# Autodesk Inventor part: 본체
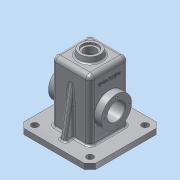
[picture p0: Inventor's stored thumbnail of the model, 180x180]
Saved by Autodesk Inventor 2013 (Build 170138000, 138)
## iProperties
Created: 2016-02
Part Number: 본체
Material: 알루미늄 6061
Document SubType Name: Modeling
Designer: Administrator
Density: 2.71 g/cm^3
Mass: 932.811 g
Surface Area: 1043.48 cm^2
Volume: 344.211 cm^3
Author: Administrator
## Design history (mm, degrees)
sketch "스케치1"
  geometry: L1 (10, 0)-(120, 0); L2 (130, 10)-(130, 120); L3 (120, 130)-(10, 130); L4 (0, 120)-(10, 130); L5 (0, 10)-(0, 120); L6 (130, 120)-(120, 130); L7 (130, 10)-(120, 0); L8 (0, 10)-(10, 0); C1 r 6 at (15, 15); C2 r 6 at (115, 15); C3 r 6 at (115, 115); C4 r 6 at (15, 115); 1 further point
  constraints: 16 end point, 5 perpendicular, 4 centre point, 1 horizontal
extrude "돌출1" new body sketch "스케치1" distance "d19" = 10; taper "d20" = 0 deg
sketch "스케치2"
  geometry: L1 (100, 65)-(100, 38); L2 (92, 30)-(38, 30); L3 (30, 38)-(30, 92); L4 (38, 100)-(92, 100); L5 (100, 92)-(100, 65); A1 r 8 centre (38, 92) between (38, 100) and (30, 92); A2 r 8 centre (92, 92) between (100, 92) and (92, 100); A3 r 8 centre (92, 38) between (92, 30) and (100, 38); A4 r 8 centre (38, 38) between (30, 38) and (38, 30); 1 further point
  constraints: 10 end point, 8 point on circle, 8 tangent, 4 centre point, 3 equal radius, 2 parallel, 1 perpendicular
extrude "돌출2" join sketch "스케치2" distance "d28" = 110; taper "d29" = 0 deg
sketch "스케치3"
  geometry: L1 (-30, 65)-(-30, 100) reference; L2 (-30, 100)-(-100, 100); L3 (-100, 100)-(-100, 30); L4 (-100, 30)-(-30, 30) reference; L5 (-30, 30)-(-30, 65) reference; L6 (-35, 95)-(-35, 65); L7 (-35, 65)-(-35, 35); L8 (-35, 35)-(-95, 35); L9 (-95, 35)-(-95, 95); L10 (-95, 95)-(-35, 95); 1 further point
  constraints: 20 end point, 4 perpendicular, 2 parallel, 2 vertical, 1 horizontal, 4 other
  dimensions: "d34" = 70 distance of L2.end L3.end; "d35" = 70 distance of L3.end L4.end; "d37" = 5 distance between parallel lines of L1 L6
extrude "돌출3" cut sketch "스케치3" distance "d38" = 115; taper "d39" = 0 deg
node "작업 평면1"
sketch "스케치4"
  geometry: L1 (30, 10)-(30, 120) reference; L2 (120, 10)-(10, 10) reference; L3 (0, 0)-(0, 10); L4 (15, 10)-(30, 95.069); L5 (30, 95.069)-(30, 10); L6 (15, 10)-(30, 10)
  constraints: 8 end point, 2 collinear, 2 point on line
  dimensions: "d42" = 10 distance of L3.start L3.end; "d43" = 15 distance of L3.end L4.start
extrude "돌출4" join sketch "스케치4" stored distance "d48" = 10; taper "d49" = 0 deg
node "작업 평면2"
sketch "스케치5"
  geometry: L1 (0, 0)-(-110, 0) reference; L2 (10, -38)-(10, 27); L3 (10, 27)-(-45, 27); L4 (0, -8)-(-110, -8) reference; C1 r 27.5 at (-45, 27)
  constraints: 4 end point, 2 perpendicular, 1 centre point, 1 coincident
  dimensions: "d51" = 65 distance of L2.start L2.end; "d52" = 55 distance of L2.end L3.end; "d53" = 55 diameter of C1
extrude "돌출5" join sketch "스케치5" distance "d54" = 13; taper "d55" = 0 deg
sketch "스케치6"
  geometry: L1 (0, 0)-(0, 60) reference; L2 (0, 60)-(115, 60) reference; L3 (0, 30)-(55, 30); C1 r 27.5 at (55, 30); 1 further point
  constraints: 2 end point, 1 centre point, 1 coincident, 1 midpoint, 1 parallel
  dimensions: "d56" = 55 distance of L3.start L3.end; "d57" = 55 diameter of C1
extrude "돌출6" join sketch "스케치6" distance "d58" = 7; taper "d59" = -45 deg
sketch "스케치7"
  geometry: C1 r 27.5 at (0, 0) reference; C2 r 16 at (0, 0); 1 further point
  constraints: 1 centre point, 1 coincident
  dimensions: "d60" = 32 diameter of C2
extrude "돌출7" cut sketch "스케치7" distance "d61" = 50; taper "d62" = 0 deg
sketch "스케치8"
  geometry: L1 (0, 0)-(-22.5, 0); C1 r 27.5 at (0, 0) reference; 1 further point
  constraints: 2 end point, 1 coincident, 1 horizontal, 1 horizontal alignment, 2 other
hole "구멍1" sketch "스케치8" at (-22.5, 0) diameter "d64" = 3.242; stored, may be unused: countersink angle "d68" = 90 deg, drill point angle "d70" = 118 deg; dims "d65" = 8, "d66" = 4, "d67" = 2, "d69" = 10
sketch "스케치9"
  geometry: C1 r 20 at (65, 65); 1 further point
  constraints: 1 centre point
  dimensions: "d75" = 40 diameter of C1
extrude "돌출8" join sketch "스케치9" distance "d76" = 10; taper "d77" = -10 deg
sketch "스케치10"
  geometry: C1 r 18.237 at (0, 0) reference; C2 r 14 at (0, 0); 1 further point
  constraints: 1 centre point, 1 coincident
  dimensions: "d78" = 28 diameter of C2
extrude "돌출9" cut sketch "스케치10" distance "d79" = 4; taper "d80" = 0 deg
sketch "스케치11"
  geometry: C1 r 14 at (0, 0) reference; C2 r 10.5 at (0, 0); 1 further point
  constraints: 1 centre point, 1 coincident
  dimensions: "d81" = 21 diameter of C2
extrude "돌출10" cut sketch "스케치11" distance "d82" = 40; taper "d83" = 0 deg
sketch "스케치12"
  geometry: L1 (-10, 8.763)-(-10, 45.237) reference; 2 further points
  constraints: 1 other
feature "엠보싱1" sketch "스케치12" dims "d85" = 0.5, "d86" = 0
chamfer "모따기1" distance "d87" = 1; stored, may be unused: second distance "d88" = 2, angle "d89" = 45 deg
fillet "모깎기1" dims "d90" = 3, "d91" = 8, "d92" = 0.5
node "솔리드1"
mirror "대칭1"
pattern_circular "원형 패턴1" dims angle "d72" = 360 deg
mirror "대칭2"
other parameters: "d40" = 65, "d50" = 65
